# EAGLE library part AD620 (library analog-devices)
Low Cost, Low Power, Instrumentation Amplifier Source: http://www.analog.com/UploadedFiles/Data_Sheets/37793330023930AD620_e.pdf
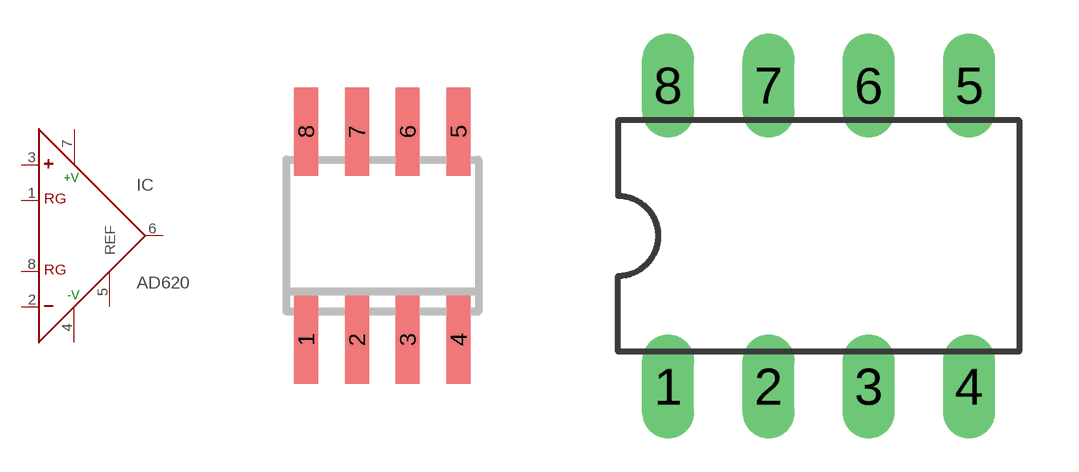
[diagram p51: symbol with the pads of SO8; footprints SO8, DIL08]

Designator prefix IC

## AD620R (MPN: AD620AR; OC_FARNELL: 1464424; OC_NEWARK: 05F7109)  [SO8]
1  RG  pas
2  -  in
3  +  in
4  -V  pwr
5  REF  pas
6  OUT  out
7  +V  pwr
8  RG  pas

## AD620N (MF: ALTERA CORPORATION; MPN: AD620AN; OC_FARNELL: 1523782; OC_NEWARK: 05F7108)  [DIL08]
Pads as for SO8

## Footprint SO8 (pad centres in mm)
8-Lead Small Outline IC (SO-8) Source: http://www.analog.com/UploadedFiles/Data_Sheets/703465986AD8611_2_0.pdf
smd 0.6 x 2.2: 1 -1.905,-2.6; 2 -0.635,-2.6; 3 0.635,-2.6; 4 1.905,-2.6; 5 1.905,2.6; 6 0.635,2.6; 7 -0.635,2.6; 8 -1.905,2.6

## Footprint DIL08 (pad centres in mm)
Dual In Line Package
drill 0.813 long: 1 -3.81,-3.81; 2 -1.27,-3.81; 3 1.27,-3.81; 4 3.81,-3.81; 5 3.81,3.81; 6 1.27,3.81; 7 -1.27,3.81; 8 -3.81,3.81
